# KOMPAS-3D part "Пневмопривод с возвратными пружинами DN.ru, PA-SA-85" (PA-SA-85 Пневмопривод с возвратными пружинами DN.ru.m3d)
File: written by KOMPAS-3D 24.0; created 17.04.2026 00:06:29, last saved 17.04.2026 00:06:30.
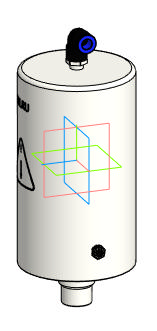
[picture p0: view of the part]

Document properties: Автор: DN.RU; Полное имя файла: D:\PROJECT CAD\DN.RU\...201(ACTUALE). PA-SA-85 Пневмопривод с возвратными пружинами DN.ru\Исходники\Шток 10мм\PA-SA-85 Пневмопривод с возвратными пружинами DN.ru.m3d

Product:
- Body: Твердое тело2  | qty 1
    Масса: 6.646189
- Part/product: Пневмопривод с возвратными пружинами DN.ru  | designation PA-SA-85
    Масса: 3.09
    Раздел спецификации: Прочие изделия
    Комментарий: D290-00344
    Примечание: D290-00344
    additional columns: Типовые

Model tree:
1. Твердое тело2  (labels: Твердое тело2)

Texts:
  PA-SA-85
